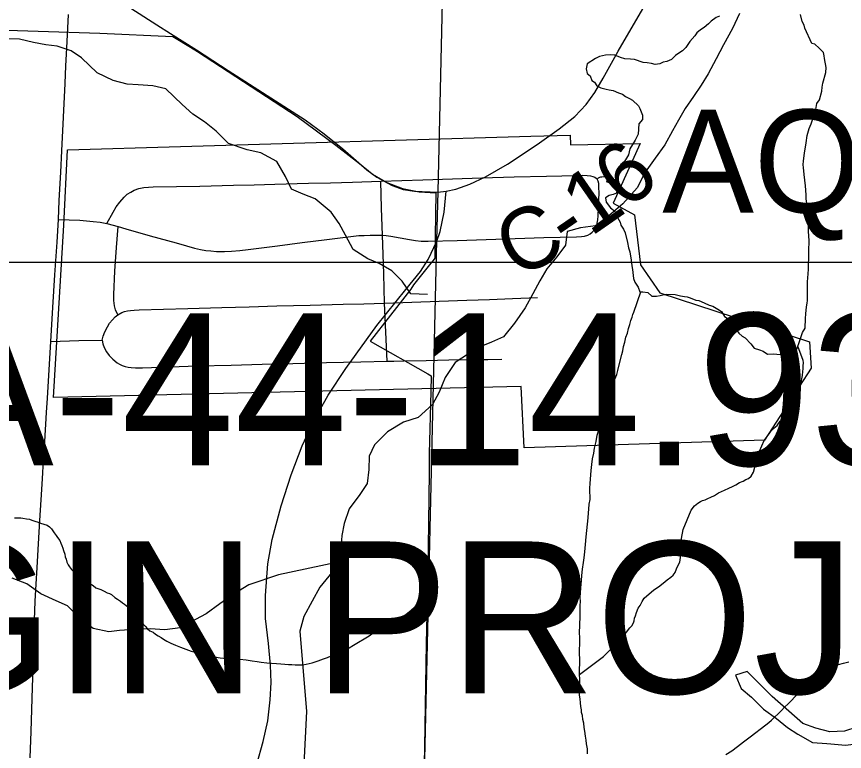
# Model space of a CAD drawing. Extents: x -6.1 to 38, y -7.7 to 22.
# Drawn here: x 7.585 to 8.348, y 17.406 to 18.083 of the extents above; entities that cross this region are included whole.
import ezdxf

# ---------------------------------------------------------------- set-up
doc = ezdxf.new("R2010")
doc.units = 0
for name, color, linetype in [('GM_X_City_Street', 7, 'Continuous'), ('GM_X_Corporation', 7, 'Continuous'), ('GM_X_Corporation_Text', 7, 'Continuous'), ('GM_X_County_Road', 7, 'Continuous'), ('GM_X_County_Road_Text', 7, 'Continuous'), ('GM_X_Minor_Lake', 7, 'Continuous'), ('GM_X_Minor_River', 7, 'Continuous'), ('SH_Text', 7, 'Continuous')]:
    doc.layers.add(name, color=color, linetype=linetype)

msp = doc.modelspace()

# ---------------------------------------------------------------- linework, layer by layer
at = {"layer": 'GM_X_City_Street'}
msp.add_line((7.66792, 17.89209), (7.67844, 17.88913), dxfattribs=at)
for points in [[(7.66792, 17.89209), (7.67378, 17.90246), (7.67654, 17.90735), (7.6799, 17.91167), (7.68402, 17.91618), (7.68672, 17.91889), (7.68998, 17.92099), (7.69327, 17.92271), (7.69752, 17.92418), (7.70219, 17.92501), (7.70635, 17.92543), (7.71071, 17.92574), (7.73215, 17.9261), (7.7536, 17.92647), (7.78467, 17.92721), (7.80377, 17.92767), (7.82287, 17.92813), (7.85393, 17.929), (7.87419, 17.92958), (7.89444, 17.93015), (7.92046, 17.93089), (7.93978, 17.93154), (7.9591, 17.93218), (7.98638, 17.93316), (8.01366, 17.93415), (8.04336, 17.93488), (8.07306, 17.93561), (8.10131, 17.93633), (8.10599, 17.93643), (8.11066, 17.93623), (8.11357, 17.93592), (8.11596, 17.9353), (8.11774, 17.93455), (8.11887, 17.93379), (8.11985, 17.93288)], [(8.11865, 17.8881), (8.11944, 17.89007), (8.11996, 17.89237), (8.12042, 17.89552), (8.12073, 17.89901), (8.12108, 17.90696), (8.12161, 17.92023), (8.12151, 17.92512), (8.12129, 17.92878), (8.12085, 17.931), (8.11985, 17.93288), (8.12103, 17.93392), (8.12229, 17.93453), (8.12316, 17.93482), (8.12407, 17.93502), (8.12584, 17.93526), (8.1286, 17.93538)], [(7.92635, 17.7651), (7.92514, 17.79182), (7.92393, 17.81853), (7.92326, 17.84577), (7.92204, 17.88116), (7.92125, 17.90602), (7.92046, 17.93089)], [(7.80624, 17.39405), (7.81191, 17.41495), (7.81626, 17.4339), (7.81866, 17.45349), (7.81931, 17.4694), (7.81887, 17.48529), (7.81692, 17.50511), (7.8143, 17.52819), (7.8143, 17.54932), (7.81626, 17.57871), (7.8204, 17.60114), (7.82867, 17.63206), (7.83782, 17.66059), (7.84805, 17.68737), (7.85872, 17.71024), (7.87201, 17.73398), (7.88812, 17.75858), (7.91687, 17.798), (7.94365, 17.83132), (7.95694, 17.84787), (7.96412, 17.85875), (7.97203, 17.87586), (7.97501, 17.88467), (7.97899, 17.90257), (7.98067, 17.92169)], [(7.62344, 17.89571), (7.64299, 17.89499), (7.64927, 17.89455), (7.65556, 17.89394), (7.66178, 17.8932), (7.66792, 17.89209)], [(7.6636, 17.7847), (7.66459, 17.78835), (7.66615, 17.79234), (7.66847, 17.79688), (7.67058, 17.8002), (7.67312, 17.80341), (7.67564, 17.80598), (7.67822, 17.80797), (7.67614, 17.81262), (7.67514, 17.81611), (7.67439, 17.82096), (7.67432, 17.82657), (7.67539, 17.84804), (7.67705, 17.86993), (7.67844, 17.88913)], [(7.67844, 17.88913), (7.68548, 17.88699), (7.70805, 17.88063), (7.73179, 17.87415), (7.74143, 17.87135), (7.7487, 17.86933), (7.75447, 17.86802), (7.75912, 17.86723), (7.76394, 17.8667), (7.76919, 17.86635), (7.77628, 17.86627), (7.78303, 17.86667), (7.79056, 17.86718), (7.79836, 17.86802), (7.8254, 17.87146), (7.84801, 17.87438), (7.87062, 17.8773), (7.89024, 17.87984), (7.89541, 17.88037), (7.90025, 17.88081), (7.90508, 17.88109), (7.91074, 17.88125), (7.91565, 17.88134), (7.92204, 17.88116), (7.92554, 17.88089), (7.92984, 17.88028), (7.94701, 17.87722), (7.95239, 17.87645), (7.9576, 17.87582), (7.96417, 17.87564), (7.99093, 17.87647), (8.01769, 17.8773), (8.04414, 17.87818), (8.0706, 17.87906), (8.10082, 17.87984), (8.10545, 17.88009), (8.10808, 17.88048), (8.1111, 17.8814), (8.11353, 17.88258), (8.1153, 17.88396), (8.11707, 17.8858), (8.11865, 17.8881)], [(7.67822, 17.80797), (7.68174, 17.8099), (7.6843, 17.81084), (7.687, 17.81151), (7.6897, 17.8119), (7.69329, 17.81223), (7.69794, 17.81244), (7.72036, 17.81309), (7.74278, 17.81373), (7.77384, 17.81462), (7.79928, 17.81535), (7.82472, 17.81607), (7.85523, 17.81686), (7.88573, 17.81765), (7.90483, 17.81809), (7.92393, 17.81853), (7.94906, 17.81944), (7.97436, 17.82034), (7.99967, 17.82125), (8.02076, 17.82216), (8.04185, 17.82308), (8.06489, 17.82385)], [(7.61644, 17.78349), (7.64217, 17.78411), (7.6636, 17.7847), (7.66426, 17.78105), (7.66548, 17.77795), (7.66769, 17.77396), (7.67024, 17.77053), (7.67352, 17.767), (7.67755, 17.7637), (7.67977, 17.76239), (7.68228, 17.76123), (7.68489, 17.76033), (7.68759, 17.75972), (7.69034, 17.75939), (7.69438, 17.75923), (7.7008, 17.75912), (7.72621, 17.75995), (7.75163, 17.76078), (7.78268, 17.76165), (7.81106, 17.76244), (7.83943, 17.76322), (7.8705, 17.76388), (7.88624, 17.76421), (7.90199, 17.76455), (7.92635, 17.7651), (7.93246, 17.76524)], [(7.93246, 17.76524), (7.94163, 17.76545), (7.96234, 17.76593), (7.98305, 17.76641), (8.00103, 17.76664), (8.01903, 17.76687), (8.03206, 17.76699)]]:
    msp.add_lwpolyline(points, dxfattribs=at)
at = {"layer": 'GM_X_Corporation'}
for points in [[(6.8881, 19.93659), (7.17492, 19.92346), (7.23616, 19.921), (8.02661, 19.88922), (8.02125, 19.70471), (8.02079, 19.68982), (8.0189, 19.62846), (7.99279, 18.77986), (7.97287, 17.92154), (7.97183, 17.87641), (7.95308, 17.06692), (7.95307, 17.06643), (7.93594, 16.3267), (7.92512, 16.10977), (7.91657, 15.91251), (7.90988, 15.74002), (7.90533, 15.62285), (7.88899, 15.0865), (7.88923, 14.89059), (7.27984, 14.90301), (6.7864, 14.92029)], [(7.49071, 18.07285), (7.66163, 18.06727), (7.72876, 18.06426), (7.74505, 18.05439), (7.75165, 18.05039), (7.84344, 17.99043), (7.87908, 17.96422), (7.90075, 17.94721), (7.91241, 17.93765), (7.91272, 17.93741), (7.92611, 17.92966), (7.94055, 17.92415), (7.95571, 17.92102), (7.97116, 17.92037), (7.97025, 17.85993), (7.96866, 17.85796), (7.96661, 17.85559), (7.95066, 17.8355), (7.94802, 17.83146), (7.91064, 17.78374), (7.96395, 17.75351), (7.96701, 17.75169), (7.96667, 17.73734), (7.96516, 17.68031), (7.96492, 17.6628), (7.96368, 17.57098), (7.96239, 17.50526), (7.96058, 17.40979), (7.95566, 17.17268)]]:
    msp.add_lwpolyline(points, dxfattribs=at)
for points in [[(8.9, 14.85918), (8.9, 19.87135), (8.53815, 19.88018), (8.02661, 19.88922), (8.02125, 19.70471), (8.02079, 19.68982), (8.0189, 19.62846), (7.99279, 18.77986), (7.97287, 17.92154), (7.97183, 17.87641), (7.95308, 17.06692), (7.95307, 17.06643), (7.93594, 16.3267), (7.92512, 16.10977), (7.91657, 15.91251), (7.90988, 15.74002), (7.90533, 15.62285), (7.88899, 15.0865), (7.88923, 14.89059), (8.1023, 14.88375), (8.27757, 14.87811), (8.6137, 14.86789)], [(7.63191, 17.9598), (8.04831, 17.97211), (8.05882, 17.97242), (8.09488, 17.97349), (8.09516, 17.9643), (8.15945, 17.96558), (8.13469, 17.91063), (8.15425, 17.90008), (8.15963, 17.85387), (8.17762, 17.82828), (8.31557, 17.78314), (8.31717, 17.75893), (8.27402, 17.69239), (8.05246, 17.68548), (8.04974, 17.74182), (7.61876, 17.73183), (7.62851, 17.89054)]]:
    msp.add_lwpolyline(points, close=True, dxfattribs=at)
at = {"layer": 'GM_X_County_Road'}
for points in [[(7.98067, 17.92169), (7.98954, 17.92348), (8.00245, 17.92822), (8.01691, 17.93509), (8.03727, 17.94669), (8.06441, 17.96487), (8.08476, 17.97918), (8.09932, 17.99066), (8.1098, 18.00161), (8.11765, 18.01272), (8.12541, 18.02576), (8.13933, 18.0508), (8.16185, 18.08959), (8.17492, 18.11332), (8.18167, 18.13248), (8.18754, 18.16602), (8.19046, 18.1861), (8.20213, 18.2601)], [(7.49345, 18.07883), (7.52389, 18.08845), (7.55134, 18.09745), (7.57594, 18.10501), (7.59131, 18.10785), (7.60906, 18.10998), (7.6287, 18.10998), (7.65118, 18.10762), (7.66395, 18.10383), (7.67649, 18.09839), (7.68998, 18.09034), (7.71411, 18.07496), (7.72682, 18.06688)], [(7.59734, 17.40008), (7.59813, 17.42433), (7.59879, 17.44449), (7.59945, 17.46466), (7.60033, 17.49136), (7.6012, 17.51807), (7.60205, 17.54413), (7.60295, 17.55974), (7.60384, 17.57535), (7.60507, 17.59693), (7.60631, 17.61852), (7.60749, 17.63763), (7.60866, 17.65676), (7.60973, 17.67405), (7.61079, 17.69135), (7.61242, 17.71786), (7.61324, 17.73114), (7.61483, 17.75731), (7.61644, 17.78349), (7.61836, 17.8145), (7.62024, 17.84472), (7.62212, 17.87495), (7.62344, 17.89571), (7.62417, 17.91316), (7.62547, 17.93933), (7.62644, 17.95896), (7.62797, 17.98999), (7.6295, 18.02103), (7.63029, 18.03719), (7.63109, 18.05334), (7.63262, 18.08437)], [(7.72682, 18.06688), (7.75055, 18.05178), (7.77989, 18.03285), (7.85063, 17.98743), (7.86837, 17.97465), (7.88541, 17.96069), (7.90753, 17.94136), (7.91688, 17.93467), (7.93102, 17.92692), (7.94121, 17.92333), (7.95149, 17.92169), (7.97308, 17.921), (7.98067, 17.92169)]]:
    msp.add_lwpolyline(points, dxfattribs=at)
at = {"layer": 'GM_X_Minor_Lake'}
for points in [[(8.23256, 18.08286), (8.22953, 18.08171), (8.22499, 18.07826), (8.22234, 18.07597), (8.21856, 18.07253), (8.21516, 18.07023), (8.21175, 18.06756), (8.20987, 18.06489), (8.20534, 18.05954), (8.20157, 18.05421), (8.19854, 18.05115), (8.19514, 18.04886), (8.19211, 18.04656), (8.18833, 18.04312), (8.18417, 18.0412), (8.18076, 18.04042), (8.17773, 18.03888), (8.17318, 18.03848), (8.16976, 18.03922), (8.16597, 18.03996), (8.16217, 18.04032), (8.15419, 18.04294), (8.1504, 18.0433), (8.14547, 18.04365), (8.14129, 18.04477), (8.13597, 18.04701), (8.13255, 18.04738), (8.12762, 18.04697), (8.12194, 18.0458), (8.11815, 18.04388), (8.11058, 18.0389), (8.10985, 18.03434), (8.11062, 18.03016), (8.11328, 18.0279), (8.11482, 18.02373), (8.11748, 18.02223), (8.11939, 18.01882), (8.12319, 18.01694), (8.12812, 18.01583), (8.13078, 18.01508), (8.13458, 18.01434), (8.13952, 18.01247), (8.14332, 18.01097), (8.14598, 18.00909), (8.14978, 18.00721), (8.15244, 18.0057), (8.15777, 18.00042), (8.1593, 17.99776), (8.1616, 17.9917), (8.16162, 17.9879), (8.15822, 17.98371), (8.1575, 17.97421), (8.15486, 17.96887), (8.14996, 17.96087), (8.14885, 17.95517), (8.14508, 17.94907), (8.14129, 17.94601), (8.14019, 17.93803), (8.13869, 17.93346), (8.13528, 17.93193), (8.13225, 17.93191), (8.12808, 17.93075)], [(8.1592, 17.82912), (8.16186, 17.82914), (8.16641, 17.8284), (8.17022, 17.82501), (8.17439, 17.82503), (8.1778, 17.82581), (8.18046, 17.8262), (8.18386, 17.82698), (8.19183, 17.82664), (8.19677, 17.82553), (8.20018, 17.82479), (8.20284, 17.82442), (8.2055, 17.82368), (8.21082, 17.82143), (8.21348, 17.82106), (8.21842, 17.81881), (8.22298, 17.81694), (8.2264, 17.81582), (8.23096, 17.81318), (8.23438, 17.81092), (8.23705, 17.80638), (8.23971, 17.80487), (8.24124, 17.80184), (8.24657, 17.79617), (8.25039, 17.79088), (8.25343, 17.78823), (8.2561, 17.78673), (8.26143, 17.78106), (8.26448, 17.77728), (8.26941, 17.77579), (8.27283, 17.77429), (8.27664, 17.77165), (8.28195, 17.77206), (8.28878, 17.77133), (8.29257, 17.77059), (8.29523, 17.77137), (8.29825, 17.77329), (8.3009, 17.77482), (8.30393, 17.77635), (8.30656, 17.78434), (8.30918, 17.79158), (8.31144, 17.79576), (8.31179, 17.8045), (8.31215, 17.80868), (8.31288, 17.81514), (8.31325, 17.81856), (8.31362, 17.82122), (8.31355, 17.83832), (8.31428, 17.84554), (8.31465, 17.8501), (8.31462, 17.85503), (8.31499, 17.85959), (8.31496, 17.86681), (8.3153, 17.87593), (8.31451, 17.88504), (8.31449, 17.8896), (8.31409, 17.89415), (8.31369, 17.89947), (8.31367, 17.90403), (8.31328, 17.90858), (8.3125, 17.91465), (8.31248, 17.91845), (8.31169, 17.9268), (8.31051, 17.93705), (8.31011, 17.94351), (8.30972, 17.94616), (8.31008, 17.94958), (8.31081, 17.9568), (8.31229, 17.96631), (8.31341, 17.97315), (8.31528, 17.97962), (8.31716, 17.98381), (8.32128, 17.99712), (8.3224, 18.00244), (8.32466, 18.00588), (8.3269, 18.01387), (8.32727, 18.01766), (8.32763, 18.02108), (8.33063, 18.03098), (8.33099, 18.03554), (8.32944, 18.04388), (8.32905, 18.04654), (8.32828, 18.04958), (8.32447, 18.05335), (8.32028, 18.05713), (8.31763, 18.05787), (8.31112, 18.07189), (8.31073, 18.07455), (8.30882, 18.07796), (8.30728, 18.0844)], [(8.12808, 17.93075), (8.13074, 17.92962), (8.13416, 17.9266), (8.13797, 17.92282), (8.1376, 17.91978), (8.13457, 17.91863), (8.13079, 17.91785), (8.12738, 17.91555), (8.12815, 17.91176), (8.13197, 17.90646), (8.13615, 17.90344), (8.13768, 17.90004), (8.13845, 17.89738), (8.14112, 17.89322), (8.14151, 17.89056), (8.14418, 17.88678), (8.14571, 17.88337), (8.14764, 17.87464), (8.1488, 17.86971), (8.14995, 17.86592), (8.15112, 17.85833), (8.1519, 17.85301), (8.15229, 17.8496), (8.15346, 17.84125), (8.15461, 17.83783), (8.15767, 17.83329), (8.1592, 17.82912)], [(8.28098, 17.45629), (8.27072, 17.4669), (8.25818, 17.4794), (8.24722, 17.47596), (8.25257, 17.46382), (8.26207, 17.45587), (8.27309, 17.44489), (8.28523, 17.43618), (8.29511, 17.42785), (8.30459, 17.42179), (8.31825, 17.41423), (8.3315, 17.41311)], [(8.3315, 17.41311), (8.33528, 17.41274), (8.34853, 17.41163), (8.36101, 17.41317), (8.37306, 17.42648), (8.38589, 17.4341), (8.3991, 17.44361), (8.40397, 17.45501), (8.39942, 17.45728), (8.39791, 17.45575), (8.38508, 17.44624), (8.37264, 17.43635), (8.35905, 17.42835), (8.34772, 17.42453), (8.3341, 17.42375), (8.32122, 17.42714), (8.30947, 17.43167), (8.28098, 17.45629)]]:
    msp.add_lwpolyline(points, dxfattribs=at)
at = {"layer": 'GM_X_Minor_River'}
for points in [[(8.25105, 18.08548), (8.24467, 18.07144), (8.23639, 18.05664), (8.22962, 18.04373), (8.22211, 18.02968), (8.21571, 18.01943), (8.20856, 18.0088), (8.20103, 17.99778), (8.19463, 17.98715), (8.18937, 17.97728), (8.18222, 17.96437), (8.17319, 17.95222), (8.16415, 17.93931), (8.15663, 17.92488), (8.14344, 17.91006), (8.13062, 17.89904), (8.11817, 17.88991), (8.10456, 17.88798), (8.0921, 17.88453), (8.09062, 17.87202), (8.08272, 17.86138), (8.0733, 17.85037), (8.0669, 17.83935), (8.06051, 17.82721), (8.05337, 17.8143), (8.04358, 17.80025), (8.03341, 17.78772), (8.02246, 17.78276), (8.01113, 17.77818), (8.00132, 17.77209), (7.98886, 17.7641), (7.97983, 17.75005), (7.9742, 17.73677), (7.96818, 17.72538), (7.95499, 17.71321), (7.94139, 17.70901), (7.92667, 17.70025), (7.91461, 17.68809), (7.90972, 17.67785), (7.90938, 17.66534), (7.90791, 17.65244), (7.90114, 17.64257), (7.89135, 17.62928), (7.88685, 17.61562), (7.88461, 17.60462), (7.88352, 17.59173), (7.88015, 17.58073), (7.87527, 17.57048), (7.86434, 17.55719), (7.8572, 17.54428), (7.84968, 17.53024), (7.84594, 17.51658), (7.85184, 17.44268)], [(7.96334, 17.82658), (7.94821, 17.8273), (7.94023, 17.83903), (7.93075, 17.84848), (7.91901, 17.85527), (7.90841, 17.85942), (7.89514, 17.8681), (7.88792, 17.88135), (7.88222, 17.89195), (7.87462, 17.90254), (7.85984, 17.91463), (7.84886, 17.91915), (7.83825, 17.92368), (7.83255, 17.93541), (7.82457, 17.94904), (7.80979, 17.95696), (7.79731, 17.95996), (7.78027, 17.9656), (7.76889, 17.97694), (7.7579, 17.98563), (7.74729, 17.99281), (7.73743, 18.0015), (7.72226, 18.01586), (7.71053, 18.01886), (7.69692, 18.01959), (7.68671, 18.02032), (7.67384, 18.02369), (7.65907, 18.03086), (7.64466, 18.04446), (7.63518, 18.05088), (7.62231, 18.0554), (7.61172, 18.0565), (7.60037, 18.05875), (7.5875, 18.06175), (7.57578, 18.0621)], [(8.13494, 17.74332), (8.13599, 17.74867), (8.13781, 17.75288), (8.13888, 17.7567), (8.13995, 17.76052), (8.14242, 17.77122), (8.1435, 17.77466), (8.14418, 17.77885), (8.14525, 17.78267), (8.14631, 17.78726), (8.14776, 17.79108), (8.14882, 17.79529), (8.1499, 17.79911), (8.15097, 17.80255), (8.15206, 17.80561), (8.15277, 17.80829), (8.15349, 17.8102), (8.16003, 17.82913)], [(8.10364, 17.47659), (8.12574, 17.49334), (8.13135, 17.49876), (8.13806, 17.50535), (8.14328, 17.51076), (8.14699, 17.51577), (8.14996, 17.51963), (8.15182, 17.52156), (8.15329, 17.52425), (8.15402, 17.52617), (8.15436, 17.52845), (8.15508, 17.53075), (8.15616, 17.53381), (8.15761, 17.53764), (8.15947, 17.54033), (8.1613, 17.54379), (8.16315, 17.54686), (8.17212, 17.55463), (8.17625, 17.55737), (8.18075, 17.56087), (8.18449, 17.56398), (8.18786, 17.56632), (8.18973, 17.56825), (8.19159, 17.57057), (8.19304, 17.57402), (8.1945, 17.57747), (8.19597, 17.58015), (8.19666, 17.58435), (8.19695, 17.58929), (8.19725, 17.59348), (8.19758, 17.59615), (8.19753, 17.59919), (8.19748, 17.60185), (8.19923, 17.61025), (8.20651, 17.62787), (8.20947, 17.63211), (8.21247, 17.63444), (8.2151, 17.63601), (8.21699, 17.6368), (8.21925, 17.63761), (8.22189, 17.63879), (8.22452, 17.63998), (8.22791, 17.64156), (8.23167, 17.64391), (8.23732, 17.64629), (8.24109, 17.64826), (8.24448, 17.64984), (8.24749, 17.65142), (8.25087, 17.65338), (8.25427, 17.65458), (8.2569, 17.65615), (8.25915, 17.65733), (8.26178, 17.65928), (8.26399, 17.66312), (8.26576, 17.67), (8.26684, 17.67344), (8.26793, 17.67612), (8.26934, 17.68223), (8.27372, 17.6922), (8.27743, 17.69721), (8.28114, 17.70222), (8.28563, 17.7061), (8.2886, 17.70995), (8.29157, 17.71343), (8.29344, 17.71498), (8.29417, 17.7169), (8.296, 17.72073), (8.29782, 17.72495), (8.30041, 17.72918), (8.30224, 17.73263), (8.30372, 17.73532), (8.30519, 17.73763), (8.30629, 17.73993), (8.30663, 17.74222), (8.30771, 17.74528), (8.3084, 17.7491), (8.30911, 17.75215), (8.30943, 17.75558), (8.30976, 17.75825), (8.30972, 17.76053), (8.31004, 17.76395), (8.30962, 17.76585), (8.3048, 17.779)], [(8.11102, 17.40372), (8.11094, 17.40828), (8.1101, 17.41283), (8.10965, 17.41624), (8.10921, 17.42004), (8.10837, 17.42458), (8.10793, 17.428), (8.10748, 17.43179), (8.10666, 17.4352), (8.10621, 17.43899), (8.1054, 17.44164), (8.10535, 17.4443), (8.10492, 17.44734), (8.10448, 17.45075), (8.10404, 17.45416), (8.1036, 17.45758), (8.10352, 17.46176), (8.10345, 17.46556), (8.10377, 17.46899), (8.10371, 17.47241), (8.10364, 17.47659), (8.10354, 17.48191), (8.10384, 17.48648), (8.10376, 17.49104), (8.10368, 17.4956), (8.1036, 17.50017), (8.1039, 17.50435), (8.1038, 17.51006), (8.10369, 17.51576), (8.10397, 17.52147), (8.10418, 17.53097), (8.10415, 17.53288), (8.10409, 17.53592), (8.10402, 17.5401), (8.10433, 17.54391), (8.10426, 17.54771), (8.10457, 17.5519), (8.10486, 17.55647), (8.10518, 17.55989), (8.1055, 17.56332), (8.1058, 17.56789), (8.10646, 17.5736), (8.10711, 17.5797), (8.10779, 17.58428), (8.10845, 17.58961), (8.10909, 17.59647), (8.10972, 17.60332), (8.11037, 17.60942), (8.11103, 17.61513), (8.11169, 17.62085), (8.11199, 17.62542), (8.1123, 17.62884), (8.1126, 17.63341), (8.11328, 17.63799), (8.11323, 17.64103), (8.11317, 17.64445), (8.1131, 17.64825), (8.1134, 17.65244), (8.11371, 17.65663), (8.11402, 17.66044), (8.11432, 17.66462), (8.11499, 17.66996), (8.11565, 17.67529), (8.11669, 17.68064), (8.11737, 17.68521), (8.11878, 17.69132), (8.11982, 17.69704), (8.12125, 17.70201), (8.12303, 17.70851), (8.12482, 17.715), (8.12698, 17.72113), (8.12879, 17.72648), (8.13096, 17.73222), (8.13241, 17.73643), (8.13387, 17.7395), (8.13494, 17.74332)], [(7.58302, 17.62087), (7.58644, 17.62093), (7.58872, 17.62097), (7.59062, 17.62063), (7.59405, 17.61993), (7.59672, 17.6196), (7.59901, 17.61888), (7.60168, 17.61778), (7.60474, 17.61708), (7.60703, 17.61598), (7.61314, 17.61419), (7.61507, 17.6127), (7.617, 17.61083), (7.61817, 17.60895), (7.61935, 17.60707), (7.62129, 17.60483), (7.62246, 17.60295), (7.62479, 17.59995), (7.62559, 17.59768), (7.62639, 17.59541), (7.62757, 17.59315), (7.62799, 17.59088), (7.62919, 17.58748), (7.62961, 17.5852), (7.63041, 17.58294), (7.63122, 17.58029), (7.63241, 17.57765), (7.63358, 17.57577), (7.63552, 17.57352), (7.63823, 17.57053), (7.6417, 17.56793), (7.64516, 17.56533), (7.64824, 17.5631), (7.65054, 17.56162), (7.65246, 17.56052), (7.65553, 17.55867), (7.65785, 17.55643), (7.66244, 17.55499), (7.6655, 17.55353), (7.66819, 17.55205), (7.67048, 17.55134), (7.6724, 17.55023), (7.67548, 17.54762), (7.67779, 17.54614), (7.68048, 17.54429), (7.6824, 17.5428), (7.68433, 17.54132), (7.68741, 17.53909), (7.68935, 17.53684), (7.69167, 17.53461), (7.69361, 17.53236), (7.69555, 17.52973)], [(7.87974, 17.57987), (7.82612, 17.56846), (7.79892, 17.55929), (7.78533, 17.55092), (7.77213, 17.54179), (7.75968, 17.53266), (7.74986, 17.52733), (7.73552, 17.51971), (7.72154, 17.51778), (7.70792, 17.51888), (7.69318, 17.51808), (7.67957, 17.51728), (7.66974, 17.51612), (7.65536, 17.51912), (7.64361, 17.52781), (7.63185, 17.5399), (7.62125, 17.54442), (7.60724, 17.55083), (7.59435, 17.56027), (7.58072, 17.56554)], [(7.69555, 17.52973), (7.7002, 17.52487), (7.70137, 17.52299), (7.7033, 17.52112), (7.70562, 17.51888), (7.70755, 17.51702), (7.71061, 17.51555), (7.71293, 17.51369), (7.71523, 17.51221), (7.71792, 17.51074), (7.72022, 17.50926), (7.72329, 17.50741), (7.72712, 17.50558), (7.73134, 17.50376), (7.73593, 17.50194), (7.7409, 17.50012), (7.74586, 17.49831), (7.75197, 17.49652), (7.75732, 17.4951), (7.76227, 17.49404), (7.76723, 17.49299), (7.77256, 17.49195), (7.77827, 17.49129), (7.78435, 17.49102), (7.79043, 17.49075), (7.79652, 17.4901), (7.80185, 17.48943), (7.80642, 17.48875), (7.81023, 17.48806), (7.81556, 17.4874), (7.81975, 17.48709), (7.82431, 17.48679), (7.82849, 17.48649), (7.83191, 17.48617), (7.83534, 17.48585), (7.83838, 17.4859), (7.84142, 17.48558), (7.84484, 17.48564), (7.84825, 17.4857), (7.85166, 17.48614), (7.85734, 17.48738), (7.86262, 17.48938), (7.86753, 17.49099), (7.8713, 17.4922), (7.87469, 17.49378), (7.87847, 17.49499), (7.88111, 17.49618), (7.88412, 17.49775), (7.88751, 17.49933), (7.89127, 17.5013), (7.89541, 17.50366), (7.90968, 17.51228), (7.91306, 17.51462), (7.91756, 17.51774), (7.9217, 17.51972), (7.92509, 17.52168), (7.92847, 17.52364), (7.93223, 17.52561), (7.93562, 17.52719), (7.93862, 17.52915), (7.94164, 17.53072), (7.94501, 17.53306), (7.94838, 17.53579), (7.95174, 17.53889), (7.95399, 17.54083), (7.95625, 17.54201), (7.95812, 17.54319), (7.95886, 17.54357)], [(8.23826, 17.40296), (8.2439, 17.40648), (8.24914, 17.41038), (8.25476, 17.41466), (8.26076, 17.41933), (8.27537, 17.43024), (8.27799, 17.43257), (8.28061, 17.43452), (8.2836, 17.43761), (8.28621, 17.44032), (8.28957, 17.44342), (8.29255, 17.44652), (8.29592, 17.44962), (8.2989, 17.45272), (8.30187, 17.45619), (8.30486, 17.45929), (8.30745, 17.46275), (8.31007, 17.46508), (8.31231, 17.4674), (8.31453, 17.47049), (8.31754, 17.47244), (8.31978, 17.47438), (8.32277, 17.4771), (8.32465, 17.47827), (8.3269, 17.47945), (8.32916, 17.48063), (8.33104, 17.48181), (8.3333, 17.48299), (8.33519, 17.4834), (8.33745, 17.48421), (8.34236, 17.48581), (8.3469, 17.48704), (8.35181, 17.48827)], [(7.85184, 17.44268), (7.84793, 17.36382)]]:
    msp.add_lwpolyline(points, dxfattribs=at)
at = {"layer": 'SH_Text'}
msp.add_lwpolyline([(7.00018, 17.85635), (8.83305, 17.85635), (8.83305, 17.19187), (7.00018, 17.19187)], close=True, dxfattribs=at)

# ---------------------------------------------------------------- texts
at = {"layer": 'GM_X_Corporation_Text'}
msp.add_text('AQUILLA', height=0.094697, rotation=0.00001, dxfattribs=at).set_placement((8.17985, 17.90204))
at = {"layer": 'GM_X_County_Road_Text'}
for s, rotation, p in [('6', 40.97589, (8.14769, 17.90329)), ('1', 34.77702, (8.11365, 17.87921)), ('C', 26.53014, (8.04497, 17.84062)), ('-', 34.44484, (8.09411, 17.86581))]:
    msp.add_text(s, height=0.05682, rotation=rotation, dxfattribs=at).set_placement(p)
at = {"layer": 'SH_Text'}
for s, p in [('GEA-44-14.93', (7.22378, 17.6692)), ('BEGIN PROJECT', (7.22378, 17.4592))]:
    msp.add_text(s, height=0.1399997, dxfattribs=at).set_placement(p)

doc.saveas('drawing.dxf')
